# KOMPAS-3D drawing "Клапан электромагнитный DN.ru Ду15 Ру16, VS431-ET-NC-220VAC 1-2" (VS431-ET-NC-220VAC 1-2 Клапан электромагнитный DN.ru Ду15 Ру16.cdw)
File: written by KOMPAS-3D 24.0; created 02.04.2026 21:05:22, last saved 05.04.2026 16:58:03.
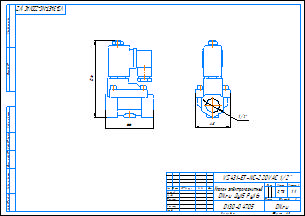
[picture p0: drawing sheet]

Document properties: c3d_UniqueCompID: ef56311e-7521-43dc-8291-0e6108b3d81d; Обозначение: VS400-ET-NC-220VAC 1-2; Наименование: Клапан электромагнитный DN.ru Ду15 Ру16; Автор: artio; Класс точности: c; Знак неуказанной шероховатости: Шероховатость не задана; Рассекать на разрезах: Да; c3d_UniqueCompID: ef56311e-7521-43dc-8291-0e6108b3d81d; Обозначение: VS400-ET-NC-220VAC 3-8; Наименование: Клапан электромагнитный DN.ru Ду10 Ру16; Автор: artio; Класс точности: c; Знак неуказанной шероховатости: Шероховатость не задана; Рассекать на разрезах: Да; Автор: artio; Форматы листов документа: A3; Полное имя файла: VS431-ET-NC-220VAC 1-2 Клапан электромагнитный DN.ru Ду15 Ру16.m3d; Масса: 0.732; Наименование: Клапан электромагнитный DN.ru Ду15 Ру16; Количество листов документа: 1; Примечание: D130-04705

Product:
- Body: Тело 1  | qty 1
    Масса: 1.030062
- Part/product: Клапан электромагнитный DN.ru Ду15 Ру16  | designation VS431-ET-NC-220VAC 1-2
    Масса: 0.732
    Раздел спецификации: Прочие изделия
    Примечание: D130-04705
    additional columns: ef56311e-7521-43dc-8291-0e6108b3d81d; VS400-ET-NC-220VAC 1-2; artio; c; Шероховатость не задана; Да

Views: Вид 1, Спереди, Проекционный вид 2
Referenced files in C:\Users\artio\OneDrive\Рабочий стол\Клапан электромагнитный DN.ru VS4x-xT-NC-x\DN10\: VS400-ET-NC-220VAC 3-8 Клапан электромагнитный DN.ru Ду10 Ру16.m3d, VS400-ET-NC-220VAC 3-8 Клапан электромагнитный DN.ru Ду10 Ру16.cdw
Referenced files in C:\Users\artio\OneDrive\Рабочий стол\Клапан электромагнитный DN.ru\VS431\VS431-ET-NC\VS431-ET-NC-220VAC\Ду15\: VS431-ET-NC-220VAC 1-2 Клапан электромагнитный DN.ru Ду15 Ру16.m3d
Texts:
  VS431-ET-NC-220VAC 1-2
  Линейный размер
  Клапан электромагнитный
  DN.ru Ду15 Ру16
  VS431-ET-NC-220VAC 1/2"
  VS431-ET-NC-220VAC 1/2"-
  Клапан электромагнитный DN.ru Ду15 Ру16
  VS431-ET-NC-220VAC 1-2 Клапан электромагнитный DN.ru Ду15 Ру16
Dimensions and other numbers on the sheet: 0; 3; 2; 4; 48; 1/2"; 66; 106; 1:1; 1; 0,73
